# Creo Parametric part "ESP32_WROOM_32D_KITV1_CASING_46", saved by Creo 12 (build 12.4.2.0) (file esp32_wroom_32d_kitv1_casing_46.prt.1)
Units: Custom; MM, KILOGRAM, SECS

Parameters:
  PTC_WM_ITERATION = "0"
  PTC_WM_VERSION = "-.0"
  PTC_WM_LIFECYCLE_STATE = "In Work"
  PTC_WM_LIFECYCLE = "MO_CADDocument"
  PTC_WM_CREATED_BY = "Maximilian Roepper (Z0017RMS: MO)"
  PTC_WM_CREATED_ON = "18-Sep-26 11:36:42 AM"
  PTC_WM_MODIFIED_BY = "Maximilian Roepper (Z0017RMS: MO)"
  PTC_WM_MODIFIED_ON = "18-Sep-26 11:36:46 AM"
  PDMLINKNUMBER = "PDM000071454977"
  PTC_WM_NAME = "esp32_wroom_32d_kitv1_casing_46.prt"
  PTC_WM_NUMBER = "PDM000071454977"

Other parameters: WEIGHT, WEIGHT_FACTOR, WEIGHT_ADD, _MASS_TEMP, _DIFF_TEMP, MC_ERRORS, SUPPLIER

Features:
  1. coordinate system
  2. datum plane "PRT_YZ"
  3. datum plane "PRT_XY"
  4. datum plane "PRT_XZ"
  5. coordinate system
  6. datum axis
  7. datum axis
  8. datum axis
  9. coordinate system
  10. imported feature
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
Other named items: PRT, SIEMENS_MO, DRW_VIEW_ORG, PRT_X, PRT_Y, PRT_Z, CS0, ROUGH_GROB

Layers: 00_STD_CSYS-KSYS, 01_STD_PLANES-EBENEN, 02_STD_AXES-ACHSEN, 03_STD_CSYS-KSYS, 24_IMPORT_FEAT-IMPORT_KE

Surfaces: 6 plane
